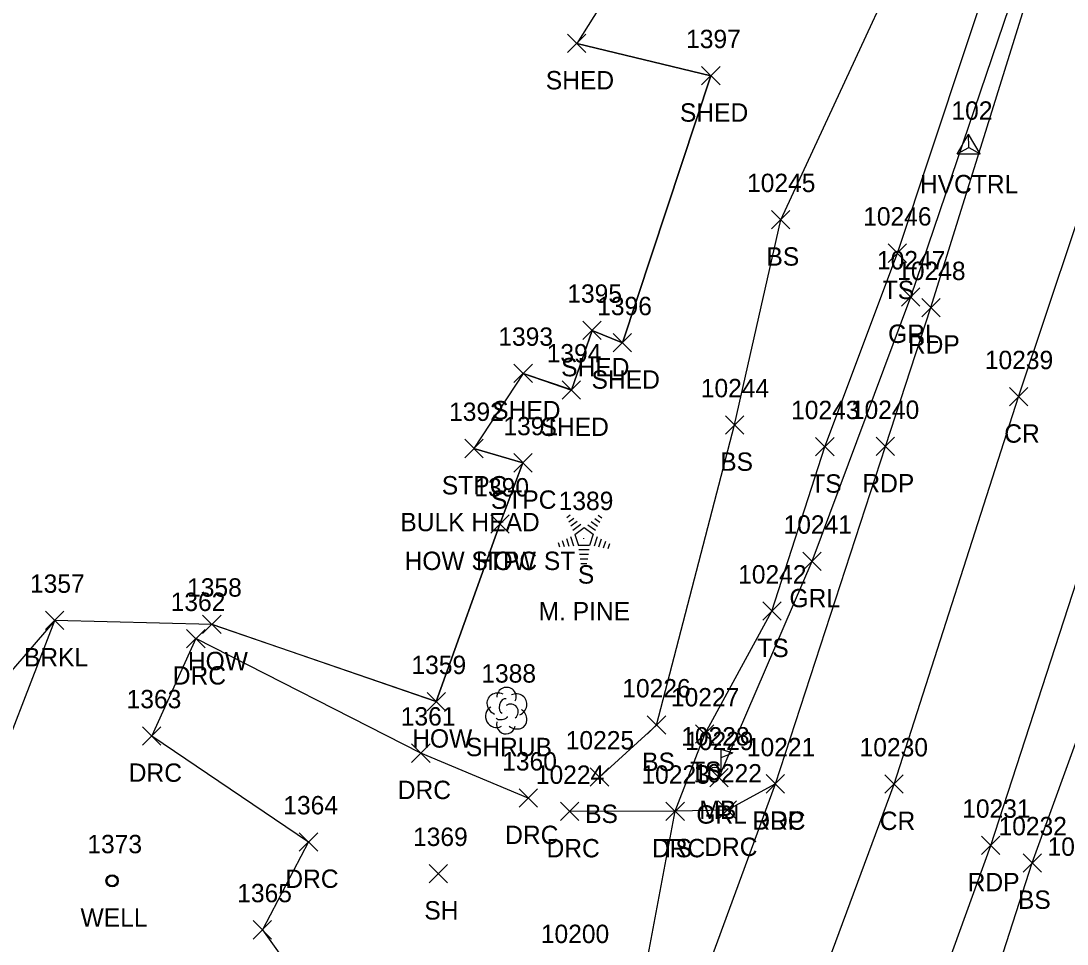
# Model space of a CAD drawing. Extents: x 1651685 to 1653558, y 889533 to 891085.
# Drawn here: x 1652677.7 to 1652791.5, y 890389.4 to 890489.8 of the extents above; entities that cross this region are included whole.
import ezdxf

# ---------------------------------------------------------------- set-up
doc = ezdxf.new("R2010")
doc.units = 0
for name, color, linetype in [('C_A', 7, 'Continuous'), ('C_I', 7, 'Continuous'), ('CPSM', 7, 'Continuous'), ('L_A', 7, 'Continuous'), ('L_C', 7, 'Continuous'), ('L_I', 7, 'Continuous'), ('L_TIC', 7, 'Continuous'), ('LAWE', 7, 'Continuous'), ('LBC', 7, 'Continuous'), ('LBF', 7, 'Continuous'), ('LELB', 7, 'Continuous'), ('LMB', 7, 'Continuous'), ('LSH', 7, 'Continuous'), ('LSOGP', 7, 'Continuous'), ('LTC', 7, 'Continuous'), ('P_A', 7, 'Continuous'), ('P_I', 7, 'Continuous'), ('P_TIC', 7, 'Continuous'), ('PET', 7, 'Continuous'), ('PRC', 7, 'Continuous'), ('R_A', 7, 'Continuous'), ('R_I', 7, 'Continuous'), ('R_TIC', 7, 'Continuous'), ('RDP', 7, 'Continuous'), ('RGR', 7, 'Continuous'), ('U_A', 7, 'Continuous'), ('U_I', 7, 'Continuous'), ('UWW', 7, 'Continuous')]:
    doc.layers.add(name, color=color, linetype=linetype)

msp = doc.modelspace()

# ---------------------------------------------------------------- linework, layer by layer
at = {"layer": 'CPSM'}
for p, q in [((1652779.53, 890475.35), (1652780.78, 890477.52)), ((1652782.03, 890475.35), (1652780.78, 890477.52)), ((1652780.79, 890476.07), (1652780.78, 890477.52)), ((1652779.53, 890475.35), (1652780.79, 890476.07)), ((1652779.53, 890475.35), (1652782.03, 890475.35)), ((1652780.79, 890476.07), (1652780.79, 890476.07)), ((1652780.79, 890476.07), (1652782.03, 890475.35))]:
    msp.add_line(p, q, dxfattribs=at)
at = {"layer": 'L_TIC'}
for points in [[(1652737.16, 890486.37), (1652739.16, 890488.37)], [(1652739.16, 890486.37), (1652737.16, 890488.37)], [(1652751.74, 890482.86), (1652753.74, 890484.86)], [(1652753.74, 890482.86), (1652751.74, 890484.86)], [(1652759.35, 890467.2), (1652761.35, 890469.2)], [(1652761.35, 890467.2), (1652759.35, 890469.2)], [(1652772.03, 890463.56), (1652774.03, 890465.56)], [(1652774.03, 890463.56), (1652772.03, 890465.56)], [(1652738.83, 890455.16), (1652740.83, 890457.16)], [(1652740.83, 890455.16), (1652738.83, 890457.16)], [(1652742.13, 890453.81), (1652744.13, 890455.81)], [(1652744.13, 890453.81), (1652742.13, 890455.81)], [(1652731.33, 890450.48), (1652733.33, 890452.48)], [(1652733.33, 890450.48), (1652731.33, 890452.48)], [(1652736.58, 890448.67), (1652738.58, 890450.67)], [(1652738.58, 890448.67), (1652736.58, 890450.67)], [(1652754.32, 890444.88), (1652756.32, 890446.88)], [(1652756.32, 890444.88), (1652754.32, 890446.88)], [(1652725.97, 890442.31), (1652727.97, 890444.31)], [(1652727.97, 890442.31), (1652725.97, 890444.31)], [(1652764.14, 890442.5), (1652766.14, 890444.5)], [(1652766.14, 890442.5), (1652764.14, 890444.5)], [(1652731.31, 890440.75), (1652733.31, 890442.75)], [(1652733.31, 890440.75), (1652731.31, 890442.75)], [(1652728.8, 890434.09), (1652730.8, 890436.09)], [(1652730.8, 890434.09), (1652728.8, 890436.09)], [(1652728.8, 890434.09), (1652730.8, 890436.09)], [(1652730.8, 890434.09), (1652728.8, 890436.09)], [(1652758.38, 890424.62), (1652760.38, 890426.62)], [(1652760.38, 890424.62), (1652758.38, 890426.62)], [(1652680.39, 890423.61), (1652682.39, 890425.61)], [(1652682.39, 890423.61), (1652680.39, 890425.61)], [(1652697.47, 890423.19), (1652699.47, 890425.19)], [(1652699.47, 890423.19), (1652697.47, 890425.19)], [(1652721.88, 890414.77), (1652723.88, 890416.77)], [(1652723.88, 890414.77), (1652721.88, 890416.77)], [(1652745.83, 890412.23), (1652747.83, 890414.23)], [(1652747.83, 890412.23), (1652745.83, 890414.23)], [(1652751.07, 890411.25), (1652753.07, 890413.25)], [(1652753.07, 890411.25), (1652751.07, 890413.25)], [(1652739.63, 890406.57), (1652741.63, 890408.57)], [(1652741.63, 890406.57), (1652739.63, 890408.57)], [(1652747.86, 890402.84), (1652749.86, 890404.84)], [(1652749.86, 890402.84), (1652747.86, 890404.84)], [(1652786.7, 890397.23), (1652788.7, 890399.23)], [(1652788.7, 890397.23), (1652786.7, 890399.23)], [(1652722.1, 890396.07), (1652724.1, 890398.07)], [(1652724.1, 890396.07), (1652722.1, 890398.07)]]:
    msp.add_lwpolyline(points, dxfattribs=at)
at = {"layer": 'LAWE'}
msp.add_lwpolyline([(1652673.4, 890326.85), (1652668.24, 890348.37), (1652662.56, 890365.27), (1652663.6, 890385.9), (1652673.62, 890404.58), (1652681.39, 890424.61)], dxfattribs=at)
at = {"layer": 'LBC'}
for points in [[(1652732.33, 890451.48), (1652737.58, 890449.67), (1652739.83, 890456.16), (1652743.13, 890454.81), (1652752.74, 890483.86), (1652738.16, 890487.37)], [(1652698.47, 890424.19), (1652722.88, 890415.77), (1652729.8, 890435.09)]]:
    msp.add_lwpolyline(points, dxfattribs=at)
at = {"layer": 'LBF'}
msp.add_lwpolyline([(1652729.8, 890435.09), (1652732.31, 890441.75), (1652726.97, 890443.31)], dxfattribs=at)
at = {"layer": 'LELB'}
for points in [[(1652740.63, 890407.57), (1652746.83, 890413.23), (1652755.32, 890445.88), (1652760.35, 890468.2), (1652780.77, 890512.23), (1652796.45, 890551.5), (1652807.59, 890577.74), (1652825.47, 890605.79), (1652840.14, 890627.46), (1652854.42, 890651.04), (1652870.71, 890668.15), (1652876.32, 890668.87), (1652880.71, 890674.05), (1652916.29, 890707.34), (1652954.78, 890736.09), (1652983.82, 890751.78), (1653022.66, 890774.83), (1653049.43, 890788.17)], [(1652703.44, 890293.38), (1652705.14, 890306.53), (1652720.51, 890335.55), (1652734.79, 890370.78), (1652740.48, 890380.18), (1652745.04, 890383.57), (1652748.86, 890403.84), (1652752.07, 890412.25), (1652759.38, 890425.62), (1652765.14, 890443.5), (1652773.03, 890464.56), (1652787.9, 890509.35)], [(1652768.84, 890309.36), (1652773.05, 890352.75), (1652787.7, 890398.23), (1652803.19, 890441), (1652820.95, 890497.33)]]:
    msp.add_lwpolyline(points, dxfattribs=at)
at = {"layer": 'LMB'}
for p, q in [((1652753.84, 890410.6), (1652755.13, 890410.22)), ((1652753.85, 890408.01), (1652753.85, 890410.6)), ((1652753.85, 890409.7), (1652755.13, 890410.21)), ((1652753.19, 890408), (1652753.19, 890408))]:
    msp.add_line(p, q, dxfattribs=at)
msp.add_circle((1652753.19, 890408), 0.656, dxfattribs=at)
at = {"layer": 'LSH'}
msp.add_line((1652730.47, 890414.84), (1652730.47, 890414.84), dxfattribs=at)
msp.add_line((1652730.47, 890414.84), (1652730.47, 890414.84), dxfattribs=at)
msp.add_arc((1652730.52, 890416.28), 1.05, 335.5272, 180.9563, dxfattribs=at)
for centre, major_axis, ratio, start_param, end_param in [((1652729.68, 890415.51), (1.21, -0.51), 0.895232, 1.570796, 4.712389), ((1652730.26, 890415.3), (-0.208, -0.792), 0.645439, 3.141593, 6.283185), ((1652731.51, 890415.43), (-1.14, -0.48), 0.949671, 1.570796, 4.712389), ((1652729.39, 890414.14), (0.58, -1.04), 0.959034, 3.141593, 6.283185), ((1652730.97, 890414.68), (-0.5, 0.667), 0.989748, 3.141593, 6.283185), ((1652730.01, 890414.09), (-0.625, -0.083), 0.423636, 0, 3.141593), ((1652731.47, 890414.01), (-1.09, 0.79), 0.841452, 1.570796, 4.712389), ((1652730.47, 890413.34), (0.26, 1.06), 0.942809, 1.570796, 4.712389)]:
    msp.add_ellipse(centre, major_axis=major_axis, ratio=ratio, start_param=start_param, end_param=end_param, dxfattribs=at)
at = {"layer": 'LSOGP'}
msp.add_lwpolyline([(1652755.23, 890514.52), (1652738.16, 890487.37), (1652752.74, 890483.86), (1652743.13, 890454.81), (1652739.83, 890456.16), (1652737.58, 890449.68), (1652732.33, 890451.47), (1652726.97, 890443.32), (1652732.31, 890441.75), (1652729.8, 890435.09), (1652722.88, 890415.78), (1652698.47, 890424.18), (1652681.39, 890424.6), (1652664.7, 890405.27), (1652645.06, 890399.57), (1652617.41, 890395.61), (1652610.62, 890392.71), (1652605.05, 890393.3), (1652601.16, 890393.28), (1652593.27, 890396.32), (1652576.59, 890388.65), (1652592.1, 890369.11), (1652560.95, 890333.56)], dxfattribs=at)
at = {"layer": 'LTC'}
for p, q in [((1652737.09, 890435.82), (1652737.44, 890436.08)), ((1652737.3, 890435.35), (1652737.83, 890435.74)), ((1652740.11, 890435.71), (1652740.66, 890435.31)), ((1652740.49, 890436.06), (1652740.9, 890435.75)), ((1652737.51, 890434.89), (1652738.21, 890435.4)), ((1652737.72, 890434.42), (1652738.59, 890435.06)), ((1652737.94, 890433.97), (1652738.95, 890434.7)), ((1652738.95, 890434.7), (1652739.95, 890433.98)), ((1652739.37, 890435.01), (1652740.18, 890434.43)), ((1652739.74, 890435.36), (1652740.42, 890434.87)), ((1652736.58, 890433.31), (1652736.79, 890432.66)), ((1652737.03, 890433.53), (1652737.3, 890432.7)), ((1652737.49, 890433.75), (1652737.82, 890432.73)), ((1652737.94, 890433.97), (1652738.33, 890432.77)), ((1652739.95, 890433.98), (1652739.56, 890432.77)), ((1652740.39, 890433.71), (1652740.05, 890432.67)), ((1652740.83, 890433.46), (1652740.54, 890432.57)), ((1652741.28, 890433.21), (1652741.04, 890432.48)), ((1652736.12, 890433.1), (1652736.27, 890432.63)), ((1652739.56, 890432.77), (1652738.33, 890432.77)), ((1652739.52, 890432.27), (1652738.38, 890432.27)), ((1652741.72, 890432.95), (1652741.53, 890432.38)), ((1652739.44, 890431.77), (1652738.45, 890431.77)), ((1652739.35, 890431.27), (1652738.52, 890431.27)), ((1652739.27, 890430.77), (1652738.59, 890430.77))]:
    msp.add_line(p, q, dxfattribs=at)
at = {"layer": 'P_TIC'}
for points in [[(1652775.68, 890457.63), (1652777.68, 890459.63)], [(1652777.68, 890457.63), (1652775.68, 890459.63)], [(1652785.21, 890447.94), (1652787.21, 890449.94)], [(1652787.21, 890447.94), (1652785.21, 890449.94)], [(1652770.73, 890442.53), (1652772.73, 890444.53)], [(1652772.73, 890442.53), (1652770.73, 890444.53)], [(1652758.76, 890405.83), (1652760.76, 890407.83)], [(1652760.76, 890405.83), (1652758.76, 890407.83)], [(1652771.67, 890405.81), (1652773.67, 890407.81)], [(1652773.67, 890405.81), (1652771.67, 890407.81)], [(1652782.18, 890399.14), (1652784.18, 890401.14)], [(1652784.18, 890399.14), (1652782.18, 890401.14)]]:
    msp.add_lwpolyline(points, dxfattribs=at)
at = {"layer": 'PET'}
for points in [[(1652703.16, 890284.22), (1652712.82, 890300.53), (1652728.55, 890330.54), (1652742.13, 890361.56), (1652749.2, 890378.01), (1652759.76, 890406.83), (1652771.73, 890443.53), (1652776.68, 890458.63), (1652791.9, 890507.53)], [(1652703.16, 890284.22), (1652712.04, 890274.26), (1652722.33, 890261.92), (1652735.14, 890284.01), (1652751.62, 890318.12), (1652767.72, 890357.35), (1652783.18, 890400.14), (1652797.7, 890444.76), (1652815.98, 890499.36)]]:
    msp.add_lwpolyline(points, dxfattribs=at)
at = {"layer": 'PRC'}
msp.add_lwpolyline([(1652712.04, 890274.26), (1652722.86, 890292.98), (1652739.69, 890324.96), (1652756.29, 890362.6), (1652772.67, 890406.81), (1652786.21, 890448.94), (1652804.54, 890503.78)], dxfattribs=at)
at = {"layer": 'R_TIC'}
for points in [[(1652773.48, 890458.79), (1652775.48, 890460.79)], [(1652775.48, 890458.79), (1652773.48, 890460.79)], [(1652762.75, 890430.04), (1652764.75, 890432.04)], [(1652764.75, 890430.04), (1652762.75, 890432.04)], [(1652695.73, 890421.63), (1652697.73, 890423.63)], [(1652697.73, 890421.63), (1652695.73, 890423.63)], [(1652690.94, 890411.05), (1652692.94, 890413.05)], [(1652692.94, 890411.05), (1652690.94, 890413.05)], [(1652720.2, 890409.17), (1652722.2, 890411.17)], [(1652722.2, 890409.17), (1652720.2, 890411.17)], [(1652752.62, 890406.5), (1652754.62, 890408.5)], [(1652754.62, 890406.5), (1652752.62, 890408.5)], [(1652758.76, 890405.83), (1652760.76, 890407.83)], [(1652760.76, 890405.83), (1652758.76, 890407.83)], [(1652731.88, 890404.28), (1652733.88, 890406.28)], [(1652733.88, 890404.28), (1652731.88, 890406.28)], [(1652736.38, 890402.83), (1652738.38, 890404.83)], [(1652738.38, 890402.83), (1652736.38, 890404.83)], [(1652747.86, 890402.84), (1652749.86, 890404.84)], [(1652749.86, 890402.84), (1652747.86, 890404.84)], [(1652753.53, 890402.98), (1652755.53, 890404.98)], [(1652755.53, 890402.98), (1652753.53, 890404.98)], [(1652707.98, 890399.51), (1652709.98, 890401.51)], [(1652709.98, 890399.51), (1652707.98, 890401.51)], [(1652702.97, 890389.95), (1652704.97, 890391.95)], [(1652704.97, 890389.95), (1652702.97, 890391.95)]]:
    msp.add_lwpolyline(points, dxfattribs=at)
at = {"layer": 'RDP'}
for points in [[(1652732.88, 890405.28), (1652721.2, 890410.17), (1652696.73, 890422.63), (1652691.94, 890412.05), (1652708.98, 890400.51), (1652703.97, 890390.95), (1652710.47, 890381.85), (1652723.32, 890377.35), (1652727.08, 890381.86)], [(1652759.76, 890406.83), (1652754.53, 890403.98), (1652748.86, 890403.84), (1652737.38, 890403.83)]]:
    msp.add_lwpolyline(points, dxfattribs=at)
at = {"layer": 'RGR'}
msp.add_lwpolyline([(1652753.62, 890407.5), (1652763.75, 890431.04), (1652774.48, 890459.79), (1652790.93, 890508.17), (1652800.51, 890534.29), (1652809.1, 890554.07), (1652821.88, 890578.18), (1652835.53, 890599.08), (1652852.44, 890621.25), (1652873.86, 890645.38), (1652894.3, 890664.88), (1652909.53, 890677.55), (1652928.71, 890692.69), (1652967.13, 890720.62), (1652991.99, 890738.03), (1653030.5, 890764.27), (1653069.01, 890789.08), (1653110.73, 890816.31), (1653147.12, 890839.54), (1653191.34, 890868.1), (1653234.07, 890895.44), (1653279.07, 890923.79), (1653318.83, 890948.74)], dxfattribs=at)
at = {"layer": 'UWW'}
for radius in [0.667, 0.625, 0.583, 0.542]:
    msp.add_circle((1652687.62, 890396.28), radius, dxfattribs=at)

# ---------------------------------------------------------------- texts
at = {"layer": 'C_A'}
msp.add_text('HVCTRL', height=2, dxfattribs=at).set_placement((1652775.48, 890471.07))
at = {"layer": 'C_I'}
msp.add_text('102', height=2, dxfattribs=at).set_placement((1652778.91, 890479.07))
at = {"layer": 'L_A'}
for s, p in [('SHED', (1652734.79, 890482.37)), ('SHED', (1652749.38, 890478.86)), ('BS', (1652758.79, 890463.2)), ('TS', (1652771.44, 890459.56)), ('SHED', (1652736.46, 890451.16)), ('SHED', (1652739.77, 890449.81)), ('SHED', (1652728.96, 890446.48)), ('SHED', (1652734.22, 890444.67)), ('BS', (1652753.76, 890440.88)), ('STPC', (1652723.48, 890438.31)), ('TS', (1652763.55, 890438.5)), ('STPC', (1652728.82, 890436.75)), ('HOW STPC ST', (1652719.43, 890430.09)), ('HOW', (1652727.18, 890430.09)), ('S', (1652738.28, 890428.61)), ('TS', (1652757.79, 890420.62)), ('BRKL', (1652678.03, 890419.61)), ('HOW', (1652695.86, 890419.19)), ('HOW', (1652720.26, 890410.77)), ('SHRUB', (1652726.1, 890409.84)), ('BS', (1652745.27, 890408.23)), ('TS', (1652750.48, 890407.25)), ('MB', (1652751.5, 890403)), ('BS', (1652739.07, 890402.57)), ('TS', (1652747.26, 890398.84)), ('BS', (1652786.14, 890393.23)), ('SH', (1652721.58, 890392.07))]:
    msp.add_text(s, height=2, dxfattribs=at).set_placement(p)
at = {"layer": 'L_C'}
for s, p in [('BULK HEAD', (1652718.97, 890434.31)), ('M. PINE', (1652734.01, 890424.61))]:
    msp.add_text(s, height=2, dxfattribs=at).set_placement(p)
at = {"layer": 'L_I'}
for s, p in [('1397', (1652750.05, 890486.86)), ('10245', (1652756.68, 890471.2)), ('10246', (1652769.31, 890467.56)), ('1395', (1652737.13, 890459.16)), ('1396', (1652740.38, 890457.81)), ('1393', (1652729.63, 890454.48)), ('1394', (1652734.89, 890452.67)), ('10244', (1652751.65, 890448.88)), ('1392', (1652724.27, 890446.31)), ('10243', (1652761.47, 890446.5)), ('1391', (1652730.18, 890444.75)), ('1390', (1652727.02, 890438.09)), ('1390', (1652727.02, 890438.09)), ('1389', (1652736.19, 890436.61)), ('10242', (1652755.71, 890428.62)), ('1357', (1652678.69, 890427.61)), ('1358', (1652695.78, 890427.19)), ('1359', (1652720.18, 890418.77)), ('1388', (1652727.78, 890417.84)), ('10226', (1652743.11, 890416.23)), ('10227', (1652748.4, 890415.25)), ('10228', (1652749.52, 890411)), ('10225', (1652736.96, 890410.57)), ('10223', (1652745.19, 890406.84)), ('10232', (1652784.03, 890401.23)), ('1369', (1652720.35, 890400.07)), ('10233', (1652789.36, 890399))]:
    msp.add_text(s, height=2, dxfattribs=at).set_placement(p)
at = {"layer": 'LTC'}
msp.add_text('.', height=1.04, rotation=270, dxfattribs=at).set_placement((1652738.83, 890433.71))
at = {"layer": 'P_A'}
for s, p in [('RDP', (1652774.17, 890453.63)), ('CR', (1652784.65, 890443.94)), ('RDP', (1652769.22, 890438.53)), ('RDP', (1652757.25, 890401.83)), ('CR', (1652771.11, 890401.81)), ('RDP', (1652780.67, 890395.14))]:
    msp.add_text(s, height=2, dxfattribs=at).set_placement(p)
at = {"layer": 'P_I'}
for s, p in [('10248', (1652773.01, 890461.63)), ('10239', (1652782.54, 890451.94)), ('10240', (1652767.97, 890446.53)), ('10221', (1652756.66, 890409.83)), ('10230', (1652768.92, 890409.81)), ('10231', (1652780.08, 890403.14))]:
    msp.add_text(s, height=2, dxfattribs=at).set_placement(p)
at = {"layer": 'R_A'}
for s, p in [('GRL', (1652772.02, 890454.79)), ('GRL', (1652761.29, 890426.04)), ('DRC', (1652694.22, 890417.63)), ('DRC', (1652689.43, 890407.05)), ('DRC', (1652718.69, 890405.17)), ('GRL', (1652751.16, 890402.5)), ('DRC', (1652757.25, 890401.83)), ('DRC', (1652730.37, 890400.28)), ('DRC', (1652734.87, 890398.83)), ('DRC', (1652746.34, 890398.84)), ('DRC', (1652752.02, 890398.98)), ('DRC', (1652706.46, 890395.51))]:
    msp.add_text(s, height=2, dxfattribs=at).set_placement(p)
at = {"layer": 'R_I'}
for s, p in [('10247', (1652770.81, 890462.79)), ('10241', (1652760.65, 890434.04)), ('1362', (1652693.99, 890425.63)), ('1363', (1652689.2, 890415.05)), ('1361', (1652719.02, 890413.17)), ('10229', (1652749.94, 890410.5)), ('10221', (1652756.66, 890409.83)), ('1360', (1652730.05, 890408.28)), ('10224', (1652733.71, 890406.83)), ('10223', (1652745.19, 890406.84)), ('10222', (1652750.86, 890406.98)), ('1364', (1652706.24, 890403.51)), ('1365', (1652701.23, 890393.95)), ('10200', (1652734.25, 890389.51))]:
    msp.add_text(s, height=2, dxfattribs=at).set_placement(p)
at = {"layer": 'U_A'}
msp.add_text('WELL', height=2, dxfattribs=at).set_placement((1652684.19, 890391.28))
at = {"layer": 'U_I'}
msp.add_text('1373', height=2, dxfattribs=at).set_placement((1652684.93, 890399.28))

doc.saveas('drawing.dxf')
